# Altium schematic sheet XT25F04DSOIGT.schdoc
size 127 x 101 mm
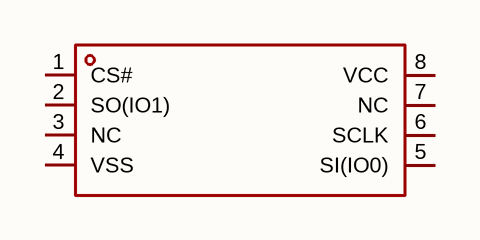
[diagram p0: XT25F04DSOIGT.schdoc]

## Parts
U?  xt25f04dsoigt  [SOP-8_L4.9-W3.9-P1.27-LS6.0-BL]  (value not drawn)

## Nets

Not connected (* = marked no-connect by the designer): U? 1(CS#) 2(SO(IO1)) 3(NC) 4(VSS) 5(SI(IO0)) 6(SCLK) 7(NC) 8(VCC)

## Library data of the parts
U? = xt25f04dsoigt: 接口类型:SPI;存储容量:4Mbit;时钟频率(fc):120MHz;; Manufacturer: XTX(芯天下); AddInBom: yes; ModelId: 75c24a7891ee4dd6bdac16a7163ff87e; ModelName: SOP-8_L4.9-W3.9-P1.27-LS6.0-BL-1; ModelTransform: 192.913,236.22,0,0,0,0,-0.393,2.749,0; Interface: SPI; Memory Size: 4Mbit; Clock Frequency: 120MHz; Voltage - Supply: 2.7V~3.6V; Standby Supply Current: 13uA; Program / Erase Cycles: 100000次; Page Programming Time (Tpp): 900us; Block Erase Time(tBE): 300ms@(32KB)；450ms@(64KB); Data Retention - TDR (Year): 20年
